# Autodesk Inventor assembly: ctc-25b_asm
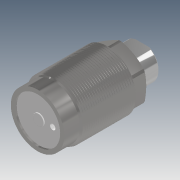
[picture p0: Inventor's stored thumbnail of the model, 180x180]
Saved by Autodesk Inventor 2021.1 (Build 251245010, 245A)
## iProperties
Created: 2018-08
Part Number: ctc-25b_asm
Description: STEP AP203
Document SubType Name: Assembly
Designer: user
Sending System: SolidWorks 2015
Preprocessor: SwSTEP 2.0
Title: ctc-25b_asm.STEP
Revision Number: ÈÎºÎ
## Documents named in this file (6)
- D:\Vault_2016\Projekty\Clamptek\Hydraulic\Dociski Hydrauliczne\Dwustronnego działania\CTC\Inventor\ctc-25b\ctc-25b_asm.iam
- D:\Vault_2016\Projekty\Clamptek\Hydraulic\Dociski Hydrauliczne\Dwustronnego działania\CTC\Inventor\ctc-25b\CTC-25BT.ipt
- D:\Vault_2016\Projekty\Clamptek\Hydraulic\Dociski Hydrauliczne\Dwustronnego działania\CTC\Inventor\ctc-25b\CTC-25BHSG.ipt
- D:\Vault_2016\Projekty\Clamptek\Hydraulic\Dociski Hydrauliczne\Dwustronnego działania\CTC\Inventor\ctc-25b\CTC-25HG.ipt
- D:\Vault_2016\Projekty\Clamptek\Hydraulic\Dociski Hydrauliczne\Dwustronnego działania\CTC\Inventor\ctc-25b\CTC-25MD.ipt
- D:\Vault_2016\Projekty\Clamptek\Hydraulic\Dociski Hydrauliczne\Dwustronnego działania\CTC\Inventor\ctc-25b\CTC-25DP.ipt
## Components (5 placed, 5 different names)
1. CTC-25BT_1
2. CTC-25BHSG_2
3. CTC-25HG_3
4. CTC-25MD_4
5. CTC-25DP_5
